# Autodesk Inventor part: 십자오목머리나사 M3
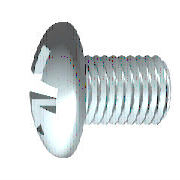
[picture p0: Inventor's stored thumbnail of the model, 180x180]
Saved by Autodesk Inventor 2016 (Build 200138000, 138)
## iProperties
Created: 2012-02
Part Number: 십자오목머리나사 M3
Material: 강철, 연강
Description: 십자 오목 머리 나사
Document SubType Name: Modeling
Standard: KS B 1023
Designer: mduedu
Standards Organization: KS
Language: ko-KR
Size Designation: A  M 3 x 6 - H
Categories: <MemberInstance><Categories><Category DisplayName="조임쇠" InternalName="e4da775c-781d-43d5-af7c-5136215cf5a6" Mnemonic="FSTN"><Category DisplayName="볼트" InternalN
Density: 7.86 g/cm^3
Appearance: 강철
Mass: 0.662353 g
Surface Area: 1.40196 cm^2
Volume: 0.0842689 cm^3
IsCustomPart: 0
Author: mduedu
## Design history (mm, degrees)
body "Solid1"
workplane "Work Plane3"
sketch "스케치2"
  geometry: L1 (-3.72, 0)-(3.72, 0) reference; L2 (0, -3.72)-(0, 3.72) reference; L3 (0, 1.5)-(0, 0); L4 (0, 0)-(1.5, 0); L5 (0, 0)-(1.879, 1.879); L6 (0.253, 1.479)-(0.261, 0.456); L7 (1.479, 0.253)-(0.456, 0.261); L8 (0.253, -1.479)-(0.261, -0.456); L9 (1.479, -0.253)-(0.456, -0.261); L10 (-0.253, 1.479)-(-0.261, 0.456); L11 (-1.479, 0.253)-(-0.456, 0.261); L12 (-1.479, -0.253)-(-0.456, -0.261); L13 (-0.253, -1.479)-(-0.261, -0.456); A1 r 0.45 centre (0, 0) between (0.45, 0) and (0, 0.45); A2 r 1.5 centre (0, 0) between (1.5, 0) and (1.479, 0.253); A3 r 1.5 centre (0, 0) between (0.253, 1.479) and (0, 1.5); A4 r 1.5 centre (0, 0) between (1.479, 0.253) and (0.253, 1.479); A5 r 1.5 centre (0, 0) between (0, -1.5) and (0.253, -1.479); A6 r 1.5 centre (0, 0) between (0.253, -1.479) and (1.479, -0.253); A7 r 1.5 centre (0, 0) between (1.479, -0.253) and (1.5, 0); A8 r 1.5 centre (0, 0) between (-1.479, 0.253) and (-1.5, 0); A9 r 1.5 centre (0, 0) between (-0.253, 1.479) and (-1.479, 0.253); A10 r 1.5 centre (0, 0) between (0, 1.5) and (-0.253, 1.479); A11 r 1.5 centre (0, 0) between (-1.5, 0) and (-1.479, -0.253); A12 r 1.5 centre (0, 0) between (-1.479, -0.253) and (-0.253, -1.479); A13 r 1.5 centre (0, 0) between (-0.253, -1.479) and (0, -1.5); A14 r 0.525 centre (0, 0) between (0.525, 0) and (0, 0.525); A15 r 0.197 centre (0.457, 0.457) between (0.261, 0.456) and (0.456, 0.261); A16 r 0.197 centre (0.457, -0.457) between (0.456, -0.261) and (0.261, -0.456); A17 r 0.197 centre (-0.457, 0.457) between (-0.456, 0.261) and (-0.261, 0.456); A18 r 0.197 centre (-0.457, -0.457) between (-0.261, -0.456) and (-0.456, -0.261); 1 further point
  constraints: 38 point on circle, 22 end point, 19 symmetric about line, 18 centre point, 4 coincident, 3 collinear, 3 point on line, 3 tangent, 1 perpendicular, 21 other
  dimensions: "d4" = 45 deg angle of L5 L4; "d5" = 0.9 diameter of A1 (= 0.3 x SDM); "d6" = 3 diameter of A4 (= SDM); "d7" = 0.2525 distance from line of L6.start L3 (= 0.5 x SBR); "d14" = 1.05 diameter of A14 (= 0.35 x SDM)
extrude "슬롯" join sketch "스케치2" taper "d15" = 5 deg; stored distance "d54" = 10
revolve "절단부" stored, may be unused: angle "d56" = 90 deg
revolve "본체" stored, may be unused: angle "d18" = 90 deg
workplane "Work Plane1"
sketch "스케치1"
  geometry: L1 (6, 0)-(6, 1.5); L2 (6, 1.5)-(1, 1.5); L3 (3.962, 5.08)-(3.962, 5.08); L4 (-2.4, 0)-(-2.4, 2.59); L5 (-2.2, 1.4)-(-1.036, 0.82); L6 (-1.036, 0.82)-(-0.6, 0); L7 (-0.6, 0)-(6, 0); L8 (-4.305, 0)-(7.717, 0) reference; L9 (0, -1.016)-(0, 6.096) reference; L10 (-2.2, 1.4)-(-2.4, 1.5); L11 (-1.636, 2.657)-(-2.4, 2.59); L12 (-1.636, 2.657)-(0, 2.8); L13 (0, 2.8)-(0, 1.347); L14 (0, 1.347)-(0.693, 1.347); L15 (0.693, 1.347)-(1, 1.5); L16 (1, 1.5)-(0, 1.5); A1 r 5 centre (2.6, 0) between (-1.636, 2.657) and (-2.4, 0)
  constraints: 28 end point, 5 point on line, 4 collinear, 4 point on circle, 3 parallel, 2 perpendicular, 1 centre point, 1 horizontal, 1 tangent
  dimensions: "d1" = 3 diameter of L2 L7 (= GD); "d2" = 1.8 distance from line of L6.end L4 (= STI); "d11" = 3 diameter of L10.end L7 (= SDM); "d12" = 62 deg angle of L6 L7; "d13" = 26.5 deg angle of L5 L7; "d17" = 5.6 diameter of L12.end L7 (= KOD); "d19" = 5 deg angle of L12 L7 (= KEWI); "d20" = 2.4 distance between parallel lines of L4 L13 (= KOH); "d21" = 5 radius of A1 (= KR); "d23" = 2.6935 diameter of L14 L7 (= BDM); "d24" = 5 distance of L1.end L2.end (= GEL); "d25" = 0.30673 horizontal distance of L14.end L2.end (= GAL); "d28" = 6 distance between parallel lines of L1 L13 (= NLG)
fillet "모깎기1" dims "d29" = 1.2 (= RR)
fillet "모깎기2" dims "d16" = 0.101 (= 0.2 x SBR)
feature "스레드" dims "d8" = 5 (= GEL), "d9" = 0
chamfer "모따기1" distance "d26" = 0.30673 (= -0.5 x SPD + 0.5 x GD); stored, may be unused: second distance "d27" = 0.30683 (computed from GUL), angle "d78" = 45 deg
other parameters: "GD" = 3 (= NND) [user parameter; used in 2 equation terms], "NLG" = 6 [user parameter; used in 1 equation term], "GEL" = 5 [user parameter; used in 2 equation terms], "KOD" = 5.6 [user parameter; used in 1 equation term], "KOH" = 2.4 [user parameter; used in 2 equation terms], "SDM" = 3 [user parameter; used in 4 equation terms], "STI" = 1.8 [user parameter; used in 1 equation term], "SBR" = 0.505 [user parameter; used in 2 equation terms], "GAL" = 0.30673 (= 0.61345 x PTC) [user parameter; used in 1 equation term], "SPD" = 2.38655 (= NND - 1.2269 x PTC) [user parameter; used in 1 equation term], "KEWI" = 5 deg [user parameter; used in 1 equation term], "d3" = -2.4 (= -KOH), "d10" = 0, "KR" = 5 [user parameter; used in 1 equation term], "BDM" = 2.6935 [user parameter; used in 1 equation term], "GUL" = 0.30673 (= 0.61345 x PTC) [user parameter; used in 1 equation term], "RR" = 1.2 [user parameter; used in 1 equation term], "d79" = 0, "d80" = 0, "PTC" = 0.5 [user parameter; used in 5 equation terms], "THREADDIA" = 3 [user parameter; used in 1 equation term], "TOA" = 30 deg [user parameter], "NND" = 3 [user parameter; used in 2 equation terms], "GD1" = 2.38655 (= THREADDIA - 1.2269 x PTC) [user parameter]
